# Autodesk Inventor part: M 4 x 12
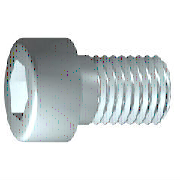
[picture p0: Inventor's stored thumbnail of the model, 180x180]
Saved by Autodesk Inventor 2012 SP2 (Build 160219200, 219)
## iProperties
IsCustomPart: 0
Created: 2009-02
Part Number: M 4 x 12
Material: 강, 연강
Description: 6각머리 태핑 나사
Document SubType Name: Modeling
Standard: KS B 1003
Designer: KYOUNG IL JANG
Standards Organization: KS
Language: ko-KR
Size Designation: M 4 x 12
Categories: <MemberInstance><Categories><Category DisplayName="조임쇠" InternalName="e4da775c-781d-43d5-af7c-5136215cf5a6" Mnemonic="FSTN"><Category DisplayName="볼트" InternalN
Density: 7.86 g/cm^3
Mass: 2.23465 g
Surface Area: 3.30853 cm^2
Volume: 0.284306 cm^3
Author: KYOUNG IL JANG
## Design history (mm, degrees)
body "Solid1"
workplane "Work Plane1"
fillet "Fillet2" dims "d30" = 0.1 (= R)
revolve "본체" stored, may be unused: angle "d10" = 90 deg
sketch "스케치2"
  geometry: L1 (0, -4.9)-(0, 4.9) reference; L2 (-4.9, 0)-(4.9, 0) reference; L3 (1.732, 0)-(0.866, -1.5); L4 (0.866, -1.5)-(-0.866, -1.5); L5 (-0.866, -1.5)-(-1.732, 0); L6 (-1.732, 0)-(-0.866, 1.5); L7 (-0.866, 1.5)-(0.866, 1.5); L8 (0.866, 1.5)-(1.732, 0); 2 further points
  constraints: 12 end point, 1 coincident, 1 horizontal alignment, 1 point on line, 12 other
extrude "슬롯" join sketch "스케치2" stored distance "d11" = 10; taper "d12" = 0 deg
fillet "모깎기1" dims "d17" = 0.4 (= RR)
feature "스레드" dims "d13" = 10.25 (= GEL), "d14" = 0
chamfer "모따기1" distance "d15" = 0.42941 (= -0.5 x SPD + 0.5 x GD); stored, may be unused: second distance "d16" = 0.42941 (= GUL), angle "d27" = 45 deg
sketch "스케치1"
  geometry: L1 (-1, 0)-(12, 0); L2 (12, 0)-(12, 2); L3 (12, 2)-(1.75, 2); L4 (1.75, 2)-(1.32, 2); L5 (1.32, 2)-(0, 2); L6 (0, 2)-(0, 3.5); L7 (0, 3.5)-(-4, 3.5); L8 (-4, 3.5)-(-4, 1.732); L9 (-4, 1.732)-(-2, 1.732); L10 (-2, 1.732)-(-1, 0); L11 (-7.2, 0)-(15.2, 0) reference; L12 (0, -0.7)-(0, 4.2) reference; L13 (1.75, 2)-(0, 2)
  constraints: 22 end point, 6 parallel, 2 collinear, 2 perpendicular, 1 horizontal, 1 point on line
  dimensions: "d1" = 10.25 distance from line of L3.end L2 (= GEL); "d2" = 0.42952 distance of L4.end L3.end (computed from GAL); "d3" = 4 distance between parallel lines of L8 L6 (= KOH); "d4" = 2 distance of L8.end L9.end (= INTI); "d5" = 60 deg angle of L10 L1; "d6" = 4 diameter of L3 L1 (= GD); "d7" = 4 diameter of L5 L1 (= BDM); "d8" = 3.4641 diameter of L9 L1 (= 1.1547 x SW); "d9" = 7 diameter of L7 L1 (= KOD); "d26" = 12 distance between parallel lines of L12 L2 (= NLG)
other parameters: "GD" = 4 (= NND) [user parameter; used in 2 equation terms], "NLG" = 12 [user parameter; used in 1 equation term], "GEL" = 10.25 [user parameter; used in 2 equation terms], "KOD" = 7 [user parameter; used in 1 equation term], "KOH" = 4 [user parameter; used in 1 equation term], "INTI" = 2 [user parameter; used in 1 equation term], "GAL" = 0.42941 (= 0.61345 x PTC) [user parameter; used in 1 equation term], "GUL" = 0.42941 (= 0.61345 x PTC) [user parameter; used in 1 equation term], "BDM" = 4 (= NND) [user parameter; used in 1 equation term], "SW" = 3 [user parameter; used in 2 equation terms], "RR" = 0.4 [user parameter; used in 1 equation term], "SPD" = 3.14117 (= NND - 1.2269 x PTC) [user parameter; used in 1 equation term], "d19" = 0, "d28" = 0, "d29" = 0, "R" = 0.1 [user parameter; used in 1 equation term], "PHH" = 0.2 [user parameter], "GD1" = 3.14117 (= THREADDIA - 1.2269 x PTC) [user parameter], "THREADDIA" = 4 [user parameter; used in 1 equation term], "FAWI" = 45 deg [user parameter], "TPU" = 14.28571 (computed from PTC) [user parameter], "PTC" = 0.7 [user parameter; used in 5 equation terms], "NND" = 4 [user parameter; used in 3 equation terms], "TOA" = 30 deg [user parameter], "E0" = 3.465 (= 1.155 x SW) [user parameter]
